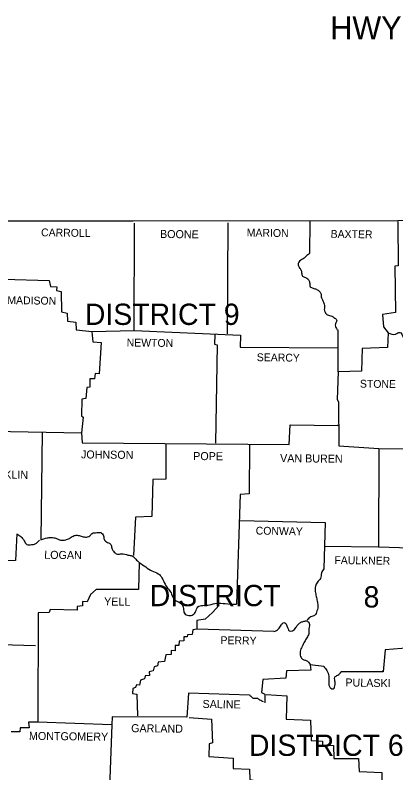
# Model space of a CAD drawing. Extents: x -2512 to 3792, y -435 to 2624.
# Drawn here: x 2800 to 2999.8, y 1667 to 2064.2 of the extents above; entities that cross this region are included whole.
import ezdxf

# ---------------------------------------------------------------- set-up
doc = ezdxf.new("R2010")
doc.units = 0
for name, color, linetype in [('1', 7, 'Continuous'), ('2', 7, 'Continuous'), ('3', 7, 'Continuous'), ('R_Border', 7, 'Continuous')]:
    doc.layers.add(name, color=color, linetype=linetype)

msp = doc.modelspace()

# ---------------------------------------------------------------- linework, layer by layer
at = {"layer": '1'}
for points in [[(2703.71, 1956.42), (2861.92, 1956.32), (3000.75, 1956.61), (3164.54, 1959.16), (3240.46, 1960.92)], [(2793.82, 1925.89), (2817.89, 1925.11), (2818.47, 1921.98), (2821.8, 1921.88), (2821.7, 1919.92), (2824.05, 1919.34), (2824.25, 1908.67), (2827.28, 1907.99), (2827.48, 1903.78), (2831.78, 1903.19), (2831.98, 1899.28), (2840.49, 1898.4), (2862.4, 1898.89), (2862.6, 1955.15)], [(2911.62, 1955.34), (2911.33, 1897.22)], [(2954.67, 1956.03), (2954.47, 1939.3)], [(3000.75, 1956.03), (3000.95, 1932.74), (2999.28, 1932.64), (2999.58, 1908.28), (2992.73, 1907.3), (2993.32, 1900.75), (2995.66, 1897.71), (2995.47, 1889.98), (2982.16, 1889.5), (2981.67, 1877.56), (2969.54, 1877.17), (2968.95, 1862.69), (2969.64, 1861.51), (2969.93, 1838.42), (2990.87, 1837.05), (2990.58, 1785.49), (3007.21, 1785), (3007.21, 1732.56), (2994.1, 1731.58), (2993.12, 1720.04), (2971.11, 1719.94)], [(2711.44, 1897.22), (2729.73, 1897.13), (2730.22, 1903.58), (2736.97, 1903.58), (2737.56, 1914.05), (2775.72, 1912.68), (2776.89, 1915.62), (2792.64, 1915.72), (2784.72, 1893.02), (2783.15, 1856.72), (2781.98, 1856.62), (2781.39, 1845.66), (2787.17, 1845.17), (2788.05, 1846.05), (2834.72, 1845.17), (2835.21, 1839.99)], [(2862.4, 1898.89), (2918.17, 1896.54), (2918.08, 1890.18), (2969.25, 1889.79)], [(2969.54, 1877.17), (2969.44, 1899.18)], [(2840.29, 1898.2), (2840.68, 1892.92), (2845.18, 1892.63), (2844.01, 1876.19), (2841.96, 1876.29), (2841.56, 1873.65), (2839.22, 1873.65), (2839.12, 1869.14), (2837.65, 1869.05), (2837.16, 1863.27), (2835.01, 1862.98), (2834.72, 1854.17), (2835.69, 1853.49), (2834.72, 1845.17)], [(2904.77, 1896.83), (2904.67, 1891.75), (2905.94, 1891.45), (2905.16, 1839.79)], [(2835.21, 1839.99), (2943.81, 1839.11), (2944.3, 1849.38), (2969.54, 1849.09)], [(2969.25, 1849.19), (2969.54, 1849.48)], [(2814.17, 1845.56), (2813.48, 1789.11)], [(2879.14, 1839.21), (2879.04, 1820.91), (2872.29, 1820.81), (2871.7, 1801.34), (2863.09, 1801.05), (2862.11, 1780.89)], [(2922.97, 1838.72), (2922.77, 1813.28), (2918.08, 1812.89), (2916.22, 1755.36)], [(2990.87, 1837.05), (3041.16, 1836.76), (3045.46, 1838.81), (3045.17, 1800.56), (3042.24, 1799.29), (3039.59, 1797.04), (3038.71, 1796.16), (3038.62, 1785.2), (3006.62, 1785.2)], [(2917.88, 1799.29), (2962.59, 1798.21), (2962.01, 1774.04)], [(2800.86, 1792.24), (2800.18, 1778.25), (2787.46, 1778.15), (2786.77, 1765.43), (2774.15, 1765.73), (2773.76, 1752.62), (2760.55, 1752.52), (2760.16, 1739.41), (2768.48, 1738.92), (2768.18, 1734.91), (2810.65, 1733.73)], [(2962.1, 1785.88), (2990.58, 1785.49)], [(2865.14, 1777.27), (2864.75, 1763.18), (2842.45, 1763.09), (2839.51, 1760.54), (2837.85, 1756.63), (2835.4, 1756.82), (2835.3, 1754.57), (2832.47, 1754.28), (2832.56, 1752.22), (2818.38, 1752.62), (2817.89, 1751.05), (2812.02, 1750.86), (2811.82, 1693.62), (2806.93, 1693.52), (2807.32, 1690.59), (2802.62, 1690.68), (2802.53, 1688.53), (2797.93, 1688.53)], [(2907.12, 1754.96), (2903.6, 1751.15), (2899.78, 1747.53), (2895.38, 1746.84), (2895.38, 1742.25), (2893.22, 1741.95), (2892.83, 1739.6), (2890.39, 1739.41), (2890.19, 1738.33), (2888.53, 1738.23), (2888.43, 1736.18), (2886.08, 1736.08), (2885.89, 1733.73), (2883.93, 1733.73), (2884.03, 1730.99), (2881.88, 1731.19), (2881.78, 1729.04), (2879.14, 1728.84), (2878.35, 1725.32), (2875.03, 1725.03), (2874.73, 1723.07), (2872.97, 1722.58), (2872.48, 1720.52), (2870.23, 1720.04), (2870.43, 1717.98), (2868.18, 1717.78), (2867.79, 1716.22), (2865.73, 1715.63), (2865.24, 1712.99), (2863.68, 1713.09), (2863.19, 1711.72), (2861.72, 1711.23), (2861.62, 1708.59), (2863.87, 1708.2), (2864.26, 1696.85)], [(2935.79, 1741.07), (2895.47, 1742.34)], [(2961.91, 1722.77), (2954.86, 1723.56), (2955.16, 1720.92), (2942.34, 1720.43), (2941.95, 1716.61), (2929.91, 1715.93), (2929.23, 1709.08), (2930.99, 1708.2), (2930.99, 1703.7)], [(2992.63, 1720.13), (2993.12, 1720.62)], [(2922.97, 1707.81), (2890.97, 1708.78), (2890.09, 1696.16), (2850.96, 1696.36), (2850.76, 1692.15)], [(2931.68, 1708.1), (2942.63, 1707.41), (2942.24, 1695.18), (2955.06, 1694.69), (2955.26, 1684.03), (2961.32, 1683.54), (2961.32, 1681.68), (2967, 1681.29), (2967.19, 1674.44), (2980.11, 1674.44), (2980.5, 1667.69), (2992.44, 1667.1), (2992.34, 1654.38)], [(2850.76, 1692.15), (2811.82, 1693.62)], [(2850.76, 1692.15), (2848.51, 1631.2)], [(2891.27, 1695.97), (2903.11, 1695.09), (2903.5, 1682.76), (2901.83, 1682.17), (2901.64, 1675.62), (2914.46, 1674.74), (2914.46, 1669.35), (2922.97, 1668.86), (2923.07, 1663.48), (2925.12, 1663.19), (2925.02, 1655.95)]]:
    msp.add_lwpolyline(points, dxfattribs=at)
for points in [[(2954.47, 1939.3), (2952.71, 1937.83), (2951.15, 1936.46), (2948.8, 1934.8), (2948.5, 1933.23), (2949.29, 1931.66), (2950.07, 1930.39), (2950.36, 1928.63), (2951.05, 1927.16), (2952.71, 1926.58), (2954.08, 1925.31), (2954.57, 1923.54), (2954.77, 1921.88), (2956.33, 1921.1), (2958.09, 1920.51), (2959.76, 1919.34), (2960.54, 1917.87), (2960.73, 1916.01), (2961.42, 1914.54), (2962.2, 1912.78), (2962.4, 1911.31), (2962.2, 1909.85), (2962.59, 1908.48), (2963.87, 1907.11), (2966.12, 1906.42), (2967.68, 1905.44), (2968.76, 1904.07), (2968.07, 1902.41), (2968.17, 1900.94), (2969.05, 1899.18)], [(2995.66, 1897.71), (2999.58, 1897.03), (3001.93, 1897.91), (3003.59, 1895.37), (3004.47, 1893.41), (3005.94, 1890.57), (3008.29, 1889.69), (3010.05, 1888.13), (3010.05, 1886.46), (3008.48, 1884.9), (3007.31, 1883.33), (3007.7, 1881.47), (3008.09, 1878.93), (3008.09, 1876.48), (3007.5, 1874.23), (3007.01, 1872.18), (3007.5, 1870.42), (3009.36, 1870.71), (3011.32, 1872.18), (3013.37, 1872.18), (3015.33, 1871.1), (3017.38, 1869.24), (3019.44, 1869.63), (3021.1, 1870.12), (3023.45, 1870.81), (3025.11, 1869.93), (3026.58, 1868.75), (3028.34, 1866.89), (3030.01, 1865.72), (3032.16, 1864.64), (3034.8, 1863.96), (3037.25, 1862.3), (3037.64, 1859.46), (3037.54, 1857.01), (3037.34, 1853.98), (3037.15, 1850.65), (3037.44, 1847.42), (3038.52, 1845.27), (3039.89, 1842.73), (3040.28, 1840.38), (3040.18, 1836.66)], [(2800.86, 1792.24), (2803.02, 1790.87), (2804.68, 1788.62), (2806.15, 1786.76), (2808.59, 1786.66), (2810.55, 1787.06), (2812.8, 1789.01)], [(2813.48, 1789.11), (2816.71, 1790.19), (2819.06, 1790.38), (2821.41, 1789.99), (2823.86, 1789.01), (2826.5, 1789.21), (2828.45, 1789.89), (2830.41, 1791.17), (2832.56, 1791.56), (2834.62, 1791.17), (2836.77, 1790.58), (2839.12, 1791.26), (2840.49, 1792.54), (2842.84, 1792.93), (2844.89, 1792.93), (2846.36, 1791.26), (2846.65, 1789.5), (2848.51, 1787.84), (2850.17, 1786.76), (2850.66, 1784.71), (2851.54, 1783.24), (2852.43, 1782.26), (2853.7, 1781.67), (2855.85, 1781.87), (2859.18, 1781.19), (2861.33, 1780.7), (2863.29, 1779.03), (2865.14, 1777.27)], [(2865.14, 1777.27), (2868.57, 1774.92), (2871.8, 1772.87), (2875.12, 1771.4), (2876.98, 1769.25), (2878.65, 1765.92), (2880.02, 1763.87), (2881.78, 1761.32), (2883.05, 1758.49), (2885.1, 1756.92), (2887.26, 1755.55), (2888.33, 1753.11), (2888.82, 1750.66), (2891.17, 1749.49), (2893.42, 1749.97), (2894.69, 1751.44), (2895.87, 1753.99), (2898.51, 1754.77), (2901.93, 1755.06), (2905.85, 1755.94), (2910.15, 1755.75), (2916.22, 1755.36)], [(2962.01, 1774.04), (2960.73, 1771.79), (2960.15, 1768.86), (2958.58, 1767), (2957.6, 1764.85), (2957.51, 1762.01), (2958, 1759.47), (2958.48, 1757.02), (2958.88, 1754.77), (2958.39, 1751.93), (2957.11, 1749.49), (2955.16, 1748.8), (2953.3, 1747.14)], [(2935.79, 1741.07), (2938.23, 1742.44), (2939.5, 1744.5), (2941.07, 1745.77), (2942.63, 1744.01), (2944, 1741.46), (2945.47, 1741.46), (2947.33, 1743.22), (2948.5, 1744.79), (2949.97, 1745.96), (2951.54, 1746.45), (2953.2, 1746.65), (2954.47, 1744.79), (2954.08, 1741.85), (2954.08, 1739.9), (2953.01, 1737.84), (2951.83, 1735.69), (2950.56, 1733.24), (2949.58, 1730.6), (2949.78, 1728.06), (2951.15, 1726.39), (2952.71, 1725.91), (2954.86, 1723.75)], [(2961.91, 1722.77), (2963.57, 1720.62), (2964.55, 1717.69), (2964.55, 1714.36), (2965.33, 1711.62), (2966.9, 1711.03), (2967.88, 1713.38), (2967.68, 1715.73), (2967.68, 1717.1), (2969.34, 1718.27), (2971.11, 1719.94)], [(2930.31, 1704.19), (2928.45, 1705.16), (2926.98, 1706.04), (2925.41, 1705.95), (2924.14, 1706.73), (2922.97, 1707.81)]]:
    msp.add_spline(points, degree=3, dxfattribs=at)

# ---------------------------------------------------------------- texts
at = {"layer": '2'}
for s, height, rotation, p in [('CARROLL', 4.109, 359.1481, (2813.58, 1948.3)), ('BOONE', 4.207, 359.4001, (2876, 1947.42)), ('MARION', 4.109, 359.1854, (2921.5, 1948.2)), ('BAXTER', 4.109, 359.2559, (2965.53, 1947.51)), ('MADISON', 4.109, 359.0906, (2795.87, 1912.78)), ('NEWTON', 4.109, 359.2717, (2858.49, 1890.57)), ('SEARCY', 4.108, 359.2527, (2926.78, 1882.84)), ('STONE', 4.108, 359.4001, (2980.89, 1868.95)), ('JOHNSON', 4.207, 359.3514, (2834.52, 1831.87)), ('POPE', 4.207, 359.6155, (2893.42, 1830.99)), ('VAN BUREN', 4.207, 359.3508, (2939.01, 1829.91)), ('FRANKLIN', 4.207, 359.1815, (2778.95, 1821.5)), ('CONWAY', 4.108, 359.0371, (2926.2, 1791.95)), ('LOGAN', 4.207, 359.3969, (2815.25, 1779.23)), ('FAULKNER', 4.109, 359.2486, (2967.49, 1776.49)), ('YELL', 4.207, 359.1987, (2846.65, 1754.77)), ('PERRY', 4.109, 359.0858, (2907.71, 1734.52)), ('PULASKI', 4.207, 359.053, (2973.26, 1712.31)), ('SALINE', 4.207, 359.1491, (2898.31, 1701.05)), ('GARLAND', 4.207, 359.3658, (2860.84, 1688.33)), ('MONTGOMERY', 4.207, 359.2944, (2807.22, 1684.32))]:
    msp.add_text(s, height=height, rotation=rotation, dxfattribs=at).set_placement(p)
at = {"layer": '3'}
for s, height, p in [('DISTRICT 9', 11.154, (2836.57, 1901.82)), ('DISTRICT', 11.154, (2870.62, 1754.38)), ('8', 11.15, (2982.85, 1753.69)), ('DISTRICT 6', 11.154, (2922.67, 1675.91))]:
    msp.add_text(s, height=height, dxfattribs=at).set_placement(p)
at = {"layer": 'R_Border'}
msp.add_text('HWYS. 82, 270 & 278 SLIDE REPAIRS (S)', height=12, dxfattribs=at).set_placement((2965.35, 2051.58))

doc.saveas('drawing.dxf')
